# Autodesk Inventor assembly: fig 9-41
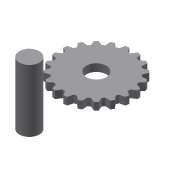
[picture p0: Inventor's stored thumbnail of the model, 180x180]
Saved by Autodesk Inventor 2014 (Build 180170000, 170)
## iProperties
Created: 2013-07
Part Number: fig 9-41
Document SubType Name: Assembly
Designer: CADCIM
Author: CADCIM
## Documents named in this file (3)
- E:\APS\Autodesk Inventor 2014-Project\inventor_2014_partfiles\Inventor_2014_prt\c09_Inv_2014_prt\c09_inv_2014_prt\fig 9-41.iam
- E:\APS\Autodesk Inventor 2014-Project\inventor_2014_partfiles\Inventor_2014_prt\c09_Inv_2014_prt\c09_inv_2014_prt\13.ipt
- E:\APS\Autodesk Inventor 2014-Project\inventor_2014_partfiles\Inventor_2014_prt\c09_Inv_2014_prt\c09_inv_2014_prt\14.ipt
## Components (2 placed, 2 different names)
1. 13:1
2. 14:1
